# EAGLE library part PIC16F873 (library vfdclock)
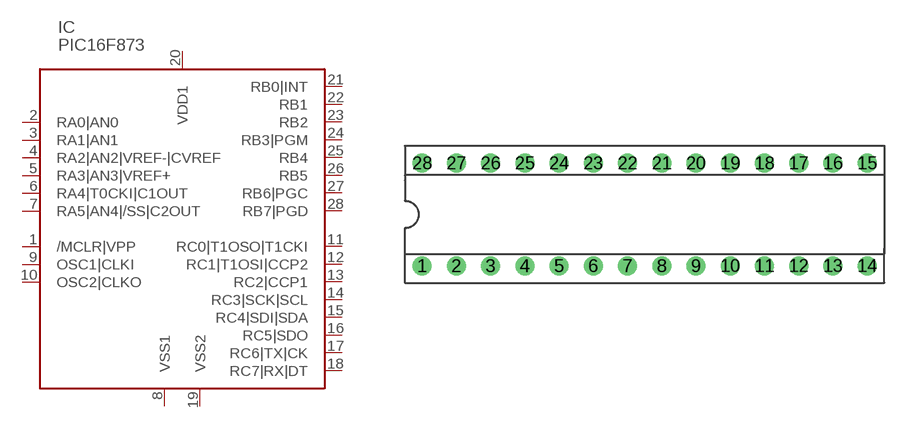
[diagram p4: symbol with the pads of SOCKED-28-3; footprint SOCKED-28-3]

Designator prefix IC

## PIC16F873A-I/SP  [SOCKED-28-3]
1  /MCLR|VPP  in
2  RA0|AN0
3  RA1|AN1
4  RA2|AN2|VREF-|CVREF
5  RA3|AN3|VREF+
6  RA4|T0CKI|C1OUT
7  RA5|AN4|/SS|C2OUT
8  VSS1  pwr
9  OSC1|CLKI  in
10  OSC2|CLKO  out
11  RC0|T1OSO|T1CKI
12  RC1|T1OSI|CCP2
13  RC2|CCP1
14  RC3|SCK|SCL
15  RC4|SDI|SDA
16  RC5|SDO
17  RC6|TX|CK
18  RC7|RX|DT
19  VSS2  pwr
20  VDD1  pwr
21  RB0|INT
22  RB1
23  RB2
24  RB3|PGM
25  RB4
26  RB5
27  RB6|PGC
28  RB7|PGD

## Footprint SOCKED-28-3 (pad centres in mm)
Dual In Line Socket Small
drill 0.9 round: 1 -16.51,-3.81; 2 -13.97,-3.81; 3 -11.43,-3.81; 4 -8.89,-3.81; 5 -6.35,-3.81; 6 -3.81,-3.81; 7 -1.27,-3.81; 8 1.27,-3.81; 9 3.81,-3.81; 10 6.35,-3.81; 11 8.89,-3.81; 12 11.43,-3.81; 13 13.97,-3.81; 14 16.51,-3.81; 15 16.51,3.81; 16 13.97,3.81; 17 11.43,3.81; 18 8.89,3.81; 19 6.35,3.81; 20 3.81,3.81; 21 1.27,3.81; 22 -1.27,3.81; 23 -3.81,3.81; 24 -6.35,3.81; 25 -8.89,3.81; 26 -11.43,3.81; 27 -13.97,3.81; 28 -16.51,3.81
